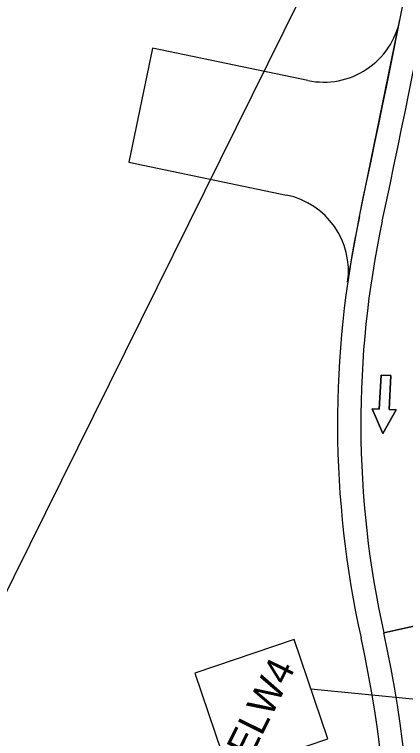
# Model space of a CAD drawing. Extents: x 14097936 to 14128734, y 8632000 to 8683104.
# Drawn here: x 14118895.5 to 14118996.1, y 8668855.4 to 8669041.8 of the extents above; entities that cross this region are included whole.
import ezdxf

# ---------------------------------------------------------------- set-up
doc = ezdxf.new("R2010")
doc.units = 0
for name, color, linetype in [('dsn_stg_shd_prev', 7, 'Continuous'), ('dsnNonPlotable', 7, 'Continuous'), ('dsnPaintExistingEdgeLineRightWhite', 7, 'Continuous'), ('dsnPaintPlaceBrokenLaneWhite', 7, 'Continuous'), ('dsnShadingPaved', 7, 'Continuous'), ('dsnStdLabel', 7, 'Continuous'), ('dsnStgShadingPrevPav', 7, 'Continuous'), ('dsnStgShadingPropPav', 7, 'Continuous'), ('dsnTapeRemoveChannelizingLaneYellow', 7, 'Continuous'), ('Level 2', 7, 'Continuous'), ('Level 5', 7, 'Continuous')]:
    doc.layers.add(name, color=color, linetype=linetype)

msp = doc.modelspace()

# ---------------------------------------------------------------- linework, layer by layer
at = {"layer": 'dsn_stg_shd_prev'}
for p, q in [((14118931.03, 8669033.2), (14118924.89, 8669003.83)), ((14118970.99, 8669024.85), (14118931.03, 8669033.2)), ((14118924.89, 8669003.83), (14118965.52, 8668995.35))]:
    msp.add_line(p, q, dxfattribs=at)
msp.add_lwpolyline([(14118981.22, 8668972.92), (14118984.25, 8668989.85), (14118994.69, 8669040.54)], dxfattribs=at)
for centre, radius, start, end in [((14115585.06, 8669716.53), 3476, 347.93292, 350.49147), ((14118975.08, 8669044.43), 20, 258.2058, 348.786), ((14118961.43, 8668975.77), 20, 351.7985, 78.2058), ((14119233.62, 8668936.54), 255, 167.9329, 192.5104), ((14123732.59, 8665873.82), 5512, 146.41866, 157.1633), ((14123732.59, 8665873.82), 5512, 146.50213, 150.36196), ((14121591.75, 8667345.11), 2876.96, 147.23629, 155.33788), ((14118697.65, 8668817.62), 294, 343.6304, 12.5104)]:
    msp.add_arc(centre, radius, start, end, dxfattribs=at)
at = {"layer": 'dsnNonPlotable'}
msp.add_lwpolyline([(14119315.27, 8668607.09), (14120010, 8670012.23), (14119557.31, 8670236.05), (14118862.58, 8668830.91)], close=True, dxfattribs=at)
at = {"layer": 'dsnPaintExistingEdgeLineRightWhite'}
for centre, radius, start, end in [((14115585.06, 8669716.53), 3482, 347.93292, 350.49147), ((14115585.06, 8669716.53), 3482, 347.93292, 350.49147), ((14119233.62, 8668936.54), 249, 167.9329, 192.5104), ((14118697.65, 8668817.62), 300, 343.6304, 12.5104)]:
    msp.add_arc(centre, radius, start, end, dxfattribs=at)
at = {"layer": 'dsnPaintPlaceBrokenLaneWhite'}
msp.add_arc((14123732.96, 8665874.38), 5500, 147.11705, 157.1633, dxfattribs=at)
at = {"layer": 'dsnShadingPaved'}
for p, q in [((14118990.53, 8668882.6), (14119002.24, 8668885.2)), ((14119002.24, 8668885.2), (14118990.53, 8668882.6))]:
    msp.add_line(p, q, dxfattribs=at)
for centre, radius, start, end in [((14115585.06, 8669716.53), 3482, 347.93292, 350.49147), ((14123732.96, 8665874.38), 5500, 145.2497, 157.1633), ((14123732.96, 8665874.38), 5488, 145.2497, 157.1633), ((14119233.62, 8668936.54), 249, 167.9329, 192.5104), ((14123732.96, 8665874.38), 5500, 146.42378, 157.1633), ((14121592.11, 8667345.68), 2876.95, 147.15737, 157.1633), ((14121592.11, 8667345.68), 2852.95, 147.15737, 157.1633), ((14123655.03, 8665915.77), 5424.12, 146.80648, 157.24675), ((14118697.65, 8668817.62), 300, 343.6304, 12.5123)]:
    msp.add_arc(centre, radius, start, end, dxfattribs=at)
at = {"layer": 'dsnStdLabel'}
msp.add_line((14119075.72, 8668858.02), (14118971.79, 8668868.09), dxfattribs=at)
msp.add_lwpolyline([(14118950.54, 8668846.65), (14118976.12, 8668855.3), (14118967.47, 8668880.88), (14118941.89, 8668872.22)], close=True, dxfattribs=at)
at = {"layer": 'dsnStgShadingPrevPav'}
for centre, radius, start, end in [((14123732.96, 8665874.38), 5512, 146.41866, 157.1633), ((14121592.12, 8667345.67), 2876.96, 147.23629, 155.33788)]:
    msp.add_arc(centre, radius, start, end, dxfattribs=at)
at = {"layer": 'dsnStgShadingPropPav'}
for centre, radius, start, end in [((14115585.06, 8669716.53), 3476, 347.93292, 350.49147), ((14119233.62, 8668936.54), 255, 167.9329, 192.5104), ((14123732.59, 8665873.82), 5512, 146.50213, 150.36196), ((14118697.65, 8668817.62), 294, 343.6304, 12.5104)]:
    msp.add_arc(centre, radius, start, end, dxfattribs=at)
at = {"layer": 'dsnTapeRemoveChannelizingLaneYellow'}
msp.add_arc((14117682.32, 8669381.12), 1500, 329.20119, 339.62671, dxfattribs=at)
at = {"layer": 'Level 2'}
msp.add_lwpolyline([(14118992.33, 8668948.84), (14118989.83, 8668948.97), (14118989.38, 8668940.23), (14118987.51, 8668940.33), (14118990.31, 8668933.93), (14118993.75, 8668940.01), (14118991.88, 8668940.1)], close=True, dxfattribs=at)
at = {"layer": 'Level 5'}
msp.add_lwpolyline([(14118991.88, 8668940.1), (14118993.75, 8668940.01), (14118990.31, 8668933.93), (14118987.51, 8668940.33), (14118989.38, 8668940.23), (14118989.83, 8668948.97), (14118992.33, 8668948.84), (14118991.88, 8668940.1)], dxfattribs=at)

# ---------------------------------------------------------------- texts
at = {"layer": 'dsnStdLabel'}
msp.add_text('ELW4', height=7.2, rotation=63.6912, dxfattribs=at).set_placement((14118956.27, 8668850.11))

doc.saveas('drawing.dxf')
